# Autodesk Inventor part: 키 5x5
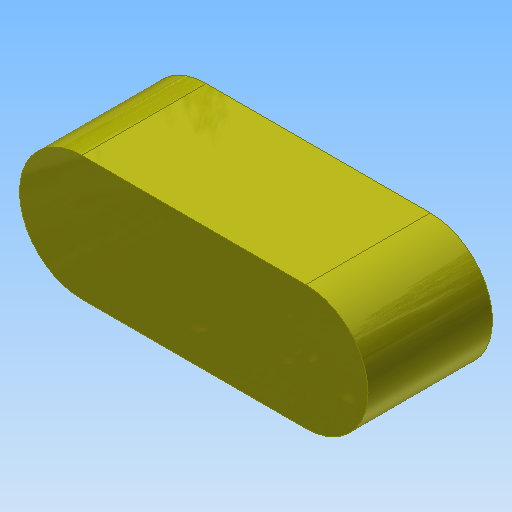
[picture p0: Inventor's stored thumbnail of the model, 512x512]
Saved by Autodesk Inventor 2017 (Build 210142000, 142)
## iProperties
Created: 2014-10
Part Number: 키 5x5
Document SubType Name: Modeling
Designer: KYOUNG IL JANG
Density: 7.86 g/cm^3
Mass: 2.54015 g
Surface Area: 2.9781 cm^2
Volume: 0.323175 cm^3
Material: 강철, 연강
Appearance: 노란색
Author: SeoGD™ [www.esajin.kr]
Revision Number: 1
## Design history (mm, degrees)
sketch "스케치1"
  geometry: L1 (-4.5, -2.5)-(4.5, -2.5); L2 (4.5, 2.5)-(-4.5, 2.5); A1 r 2.5 centre (4.5, 0) between (4.5, -2.5) and (4.5, 2.5); A2 r 2.5 centre (-4.5, 0) between (-4.5, 2.5) and (-4.5, -2.5); 2 further points
  constraints: 4 end point, 4 point on circle, 4 tangent, 2 centre point, 1 horizontal, 1 horizontal alignment, 1 midpoint, 1 parallel, 1 vertical alignment
  dimensions: "d0" = 5 distance between parallel lines of L1 L2; "d1" = 14 dimension on A1 A2
extrude "돌출1" new body sketch "스케치1" stored distance "d2" = 5; taper "d3" = 0 deg
node "솔리드1"
